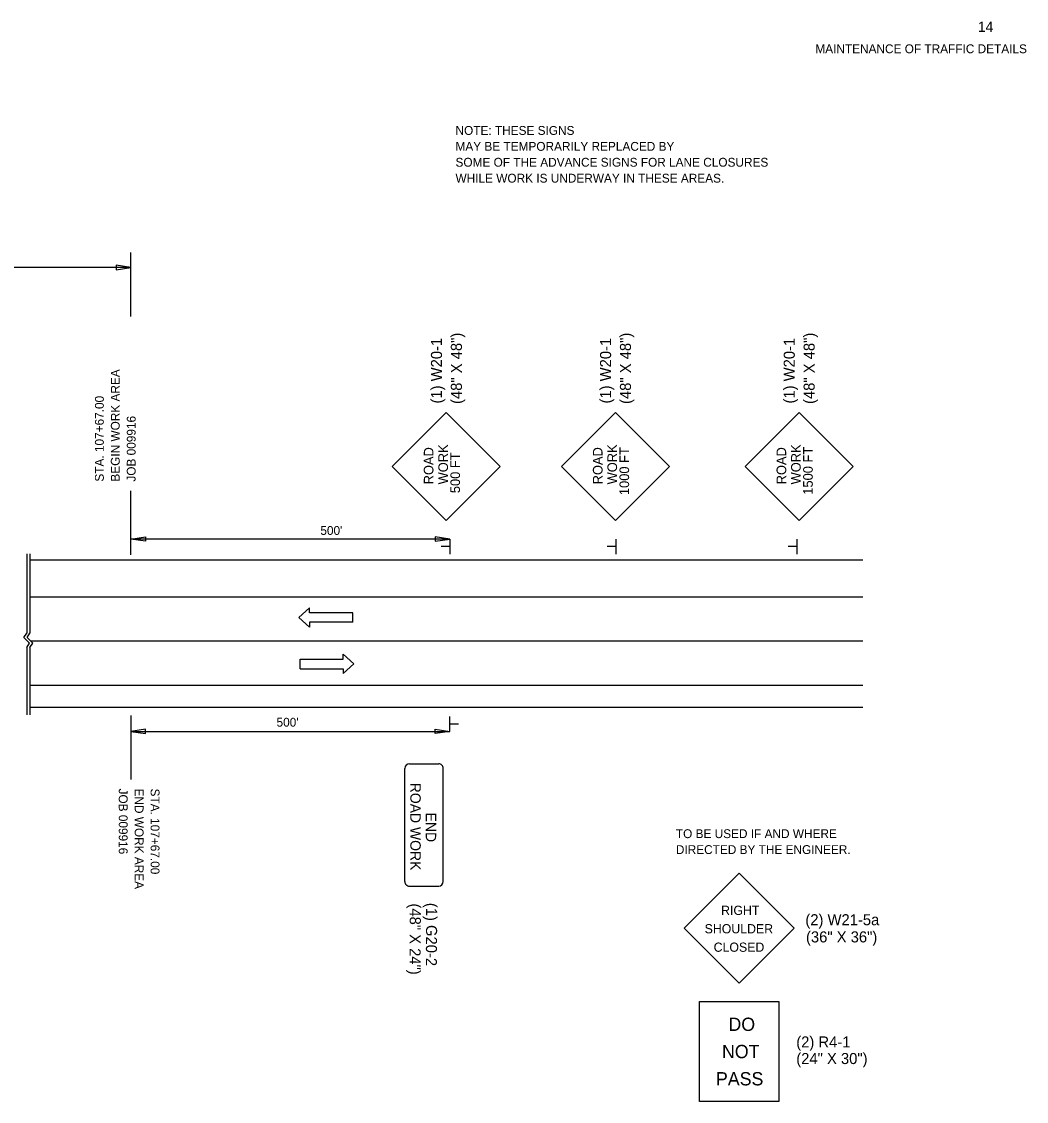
# Model space of a CAD drawing. Extents: x -900 to -62, y -12423 to -11428.
# Drawn here: x -349 to -76.3, y -12144.3 to -11851.1 of the extents above; entities that cross this region are included whole.
import ezdxf

# ---------------------------------------------------------------- set-up
doc = ezdxf.new("R2010")
doc.units = 0
for name, color, linetype in [('1', 7, 'Continuous'), ('R_MOT', 7, 'Continuous'), ('R_No Plot', 7, 'Continuous')]:
    doc.layers.add(name, color=color, linetype=linetype)

msp = doc.modelspace()

# ---------------------------------------------------------------- linework, layer by layer
at = {"layer": '1'}
for p, q in [((-319.31, -11931.22), (-319.31, -11913.78)), ((-319.31, -11917.87), (-465.9, -11917.87)), ((-319.31, -11995.93), (-319.31, -11978.49)), ((-232.76, -11991.59), (-319.31, -11991.59)), ((-232.76, -11991.61), (-232.76, -11995.67)), ((-187.68, -11991.61), (-187.68, -11995.67)), ((-138.59, -11991.61), (-138.59, -11995.67)), ((-347.58, -11995.6), (-347.58, -12017.17)), ((-346.71, -11995.6), (-346.71, -12017.17)), ((-232.76, -11993.64), (-235.13, -11993.64)), ((-187.68, -11993.64), (-190.04, -11993.64)), ((-138.59, -11993.64), (-140.95, -11993.64)), ((-120.72, -11997.34), (-346.71, -11997.34)), ((-120.72, -12007.34), (-346.71, -12007.34)), ((-348.35, -12018.32), (-347.58, -12017.17)), ((-346.82, -12019.85), (-348.35, -12018.32)), ((-347.48, -12018.32), (-346.71, -12017.17)), ((-345.95, -12019.85), (-347.48, -12018.32)), ((-120.72, -12019.34), (-346.46, -12019.34)), ((-347.58, -12021), (-346.82, -12019.85)), ((-347.58, -12021), (-347.58, -12039.34)), ((-346.71, -12021), (-345.95, -12019.85)), ((-346.71, -12021), (-346.71, -12039.34)), ((-120.72, -12031.34), (-346.71, -12031.34)), ((-120.72, -12037.34), (-346.71, -12037.34)), ((-319.31, -12039.48), (-319.31, -12056.91)), ((-232.76, -12043.81), (-232.76, -12039.74)), ((-232.76, -12041.78), (-230.39, -12041.78)), ((-319.31, -12043.81), (-232.76, -12043.81))]:
    msp.add_line(p, q, dxfattribs=at)
for points in [[(-323.27, -11918.47), (-319.31, -11917.87), (-323.27, -11917.27)], [(-315.35, -11992.19), (-319.31, -11991.59), (-315.35, -11990.99)], [(-236.72, -11992.19), (-232.76, -11991.59), (-236.72, -11990.99)], [(-315.35, -12043.21), (-319.31, -12043.81), (-315.35, -12044.41)], [(-236.72, -12043.21), (-232.76, -12043.81), (-236.72, -12044.41)]]:
    msp.add_lwpolyline(points, close=True, dxfattribs=at)
at = {"layer": 'R_MOT'}
for p, q in [((-233.71, -11957.22), (-248.37, -11971.88)), ((-233.71, -11957.22), (-219.06, -11971.88)), ((-187.82, -11957.22), (-202.48, -11971.88)), ((-187.82, -11957.22), (-173.18, -11971.88)), ((-137.99, -11957.22), (-152.64, -11971.88)), ((-137.99, -11957.22), (-123.34, -11971.88)), ((-248.37, -11971.88), (-233.71, -11986.54)), ((-219.06, -11971.88), (-233.71, -11986.54)), ((-202.48, -11971.88), (-187.82, -11986.54)), ((-173.18, -11971.88), (-187.82, -11986.54)), ((-152.64, -11971.88), (-137.98, -11986.54)), ((-123.34, -11971.88), (-137.98, -11986.54)), ((-273.7, -12012.91), (-270.82, -12010.29)), ((-270.82, -12011.6), (-270.82, -12010.29)), ((-270.82, -12015.52), (-273.7, -12012.91)), ((-259.07, -12011.6), (-270.82, -12011.6)), ((-259.07, -12014.21), (-259.07, -12011.6)), ((-259.07, -12014.21), (-270.82, -12014.21)), ((-270.82, -12014.21), (-270.82, -12015.52)), ((-273.41, -12024.18), (-261.66, -12024.18)), ((-273.41, -12026.79), (-273.41, -12024.18)), ((-261.66, -12024.18), (-261.66, -12022.87)), ((-258.79, -12025.48), (-261.66, -12022.87)), ((-273.41, -12026.79), (-261.66, -12026.79)), ((-261.66, -12028.1), (-258.79, -12025.48)), ((-261.66, -12026.79), (-261.66, -12028.1)), ((-244.96, -12084.57), (-244.96, -12053.86)), ((-243.71, -12052.61), (-235.78, -12052.61)), ((-234.53, -12084.57), (-234.53, -12053.86)), ((-243.71, -12085.82), (-235.78, -12085.82))]:
    msp.add_line(p, q, dxfattribs=at)
for points in [[(-169.19, -12097.27), (-154.27, -12082.34), (-139.35, -12097.27), (-154.27, -12112.19)], [(-143.52, -12117.19), (-143.52, -12144.27), (-165.01, -12144.27), (-165.01, -12117.19)]]:
    msp.add_lwpolyline(points, close=True, dxfattribs=at)
for centre, start, end in [((-243.71, -12053.86), 90.0014, 180.0003), ((-235.78, -12053.86), 0.0003, 90.0014), ((-243.71, -12084.57), 180.0003, 270.0014), ((-235.78, -12084.57), 270.0014, 0.0003)]:
    msp.add_arc(centre, 1.25, start, end, dxfattribs=at)

# ---------------------------------------------------------------- texts
at = {"layer": '1'}
for s, p in [('MAINTENANCE OF TRAFFIC DETAILS', (-133.57, -11859.7)), ('NOTE: THESE SIGNS', (-231.22, -11881.87)), ('MAY BE TEMPORARILY REPLACED BY', (-231.22, -11886.19)), ('SOME OF THE ADVANCE SIGNS FOR LANE CLOSURES', (-231.22, -11890.51)), ('WHILE WORK IS UNDERWAY IN THESE AREAS.', (-231.22, -11894.83)), ("500'", (-267.89, -11990.47)), ('TO BE USED IF AND WHERE', (-171.42, -12072.79)), ('DIRECTED BY THE ENGINEER.', (-171.42, -12077.11))]:
    msp.add_text(s, height=2.4, dxfattribs=at).set_placement(p)
for s, rotation, p in [('BEGIN WORK AREA ', 90, (-322.34, -11976.01)), ('STA. 107+67.00', 90, (-326.66, -11976.01)), ('JOB 009916', 90, (-318.02, -11976.01)), ("500'", 360, (-279.78, -12042.53)), ('JOB 009916', 270, (-322.59, -12059.34)), ('END WORK AREA ', 270, (-318.27, -12059.34)), ('STA. 107+67.00', 270, (-313.95, -12059.34))]:
    msp.add_text(s, height=2.4, rotation=rotation, dxfattribs=at).set_placement(p)
at = {"layer": 'R_MOT'}
for s, height, rotation, p in [('(1) W20-1', 3, 90, (-234.88, -11954.8)), ('(48" X 48")', 3, 90, (-229.48, -11954.93)), ('(1) W20-1', 3, 90, (-189, -11954.8)), ('(48" X 48")', 3, 90, (-183.6, -11954.93)), ('(1) W20-1', 3, 90, (-139.16, -11954.8)), ('(48" X 48")', 3, 90, (-133.76, -11954.93)), ('WORK', 2.613, 90, (-233.26, -11976.76)), ('WORK', 2.613, 90, (-187.38, -11976.76)), ('WORK', 2.613, 90, (-137.54, -11976.76)), ('ROAD', 2.613, 90.0004, (-237.21, -11976.75)), ('500 FT', 2.613, 90, (-229.99, -11979.14)), ('ROAD', 2.613, 90.0004, (-191.32, -11976.75)), ('1000 FT', 2.613, 90, (-184.11, -11979.67)), ('ROAD', 2.613, 90.0004, (-141.48, -11976.75)), ('1500 FT', 2.613, 90, (-134.27, -11979.57)), ('ROAD WORK', 2.835, 270.0006, (-243.49, -12057.76)), ('END', 2.835, 270.0006, (-239.3, -12065.88)), ('(48" X 24")', 3, 269.6927, (-243.61, -12090.53)), ('(1) G20-2', 3, 269.6927, (-239.18, -12090.36))]:
    msp.add_text(s, height=height, rotation=rotation, dxfattribs=at).set_placement(p)
for s, height, p in [('RIGHT', 2.5, (-159.15, -12093.65)), ('(2) W21-5a', 3, (-136.28, -12096.45)), ('SHOULDER', 2.5, (-163.61, -12098.65)), ('(36" X 36")', 3, (-136.11, -12101.11)), ('CLOSED', 2.5, (-161.17, -12103.65)), ('DO', 3.605, (-157.15, -12125.14)), ('(2) R4-1', 2.999, (-138.75, -12129.63)), ('NOT', 3.605, (-158.91, -12132.53)), ('(24" X 30")', 2.9995, (-138.75, -12134.13)), ('PASS', 3.605, (-160.54, -12139.93))]:
    msp.add_text(s, height=height, dxfattribs=at).set_placement(p)
at = {"layer": 'R_No Plot'}
msp.add_text('14', height=2.8, dxfattribs=at).set_placement((-89.46, -11853.92))

doc.saveas('drawing.dxf')
